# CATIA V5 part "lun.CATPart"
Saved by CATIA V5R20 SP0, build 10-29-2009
Part number: Part1
Material "Bathroom Floor": density 2770 kg/m3, Young's modulus 6e+10 Pa, Poisson ratio 0.3
Material "DS Red": density 7860 kg/m3, Young's modulus 2e+11 Pa, Poisson ratio 0.266
Material "Dull Green": density 7860 kg/m3, Young's modulus 2e+11 Pa, Poisson ratio 0.266
Bounding box of the stored display mesh (mm): x 0 to 50, y -115 to 115, z -114.805 to 114.805
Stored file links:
  C:\Users\asus\Desktop\180211401-刘畅\新建文件夹\lun.CATPart
  D:\Program Files\Dassault Systemes\B20\win_b64\startup\materials\Catalog.CATMaterial
  D:\Program Files\Dassault Systemes\B20\win_b64\startup\materials\red_env_512x512.jpg
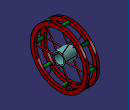
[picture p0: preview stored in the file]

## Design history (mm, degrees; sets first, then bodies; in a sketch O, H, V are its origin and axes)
Body1 (main body), material "Bathroom Floor"
  Sketch1 on yz-plane, origin (0, 0, 0), H (0, 1, 0), V (0, 0, 1)
    circle A1 centre (0, 0) radius 20
    radius A1 = 20
  Sketch2 on yz-plane, origin (0, 0, 0), H (0, 1, 0), V (0, 0, 1)
    circle A1 centre (0, 0) radius 25
    radius A1 = 25
  Pad1: profile Sketch2, direction (1, 0, 0), length 50
  Pocket1: profile Sketch1, direction (1, 0, 0), length 50
Body2, material "DS Red"
  Plane1: type Offset, RefPlane yz-plane, Offset 5
  Plane2: type Angle, RefPlane Plane1, Direction Z axis, Angle 90
  Plane3: type Offset, RefPlane zx-plane, Offset 25
  Sketch3 on Plane3, origin (0, 25, 0), H (-1, 0, 0), V (0, 0, 1)
    circle A1 centre (-2.3731, 0) radius 2
    point P1 (-2.3731, 0)
    radius A1 = 2
    coincidence: P1 H
  Pad2: profile Sketch3, direction (0, 1, 0), length 75
  CircPattern1: of Pad2, instances 6, angular step 60, axis from X axis
  Sketch4 on Plane1, origin (5, 0, 0), H (0, 1, 0), V (0, 0, 1)
    circle A1 centre (0, 0) radius 100
    point P1 (100, 0)
    circle A2 centre (0, 0) radius 115
    radius A1 = 100
    radius A2 = 115
    coincidence: A1 P1, P1 H
  Pad3: profile Sketch4, direction (1, 0, 0), length 5, mirrored extent
  Mirror1: of the body so far, about {plane type Offset, RefPlane yz-plane, Offset 25}
Body3, material "Dull Green"
  Plane4: type Offset, RefPlane yz-plane, Offset 10
  Plane5: type Offset, RefPlane xy-plane, Offset 106
  Sketch5 on Plane5, origin (0, 0, 106), H (1, 0, 0), V (0, 1, 0)
    line L1 (0, 118.9358) -> (0, -132.687)
    point P1 (0, 118.9358)
    coincidence: P1 V
    vertical: L1 V
  Plane6: type Angle, RefPlane Plane5, Direction Sketch5, Angle 90
  Plane7: type Offset, RefPlane Plane6, Offset 10, reversed
  Sketch6 on Plane7, origin (10, 0, 0), H (0, -1, 0), V (0, 0, 1)
    circle A1 centre (0, 107.363) radius 6.9477
    point P1 (0, 107.363)
    coincidence: P1 V
  Pad4: profile Sketch6, direction (1, 0, 0), length 30
  Plane8: type Offset, RefPlane Plane7, Offset 2, reversed
  Sketch7 on Plane8, origin (12, 0, 0), H (0, -1, 0), V (0, 0, 1)
    arc A1 centre (9.1664, 107.7326) radius 8.6941 from (1.3385, 111.5155) to (15.0966, 101.3749) ccw
  Pocket2: profile Sketch7, direction (1, 0, 0), length 26
  CircPattern2: of the body so far, instances 8, angular step 45, axis from X axis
